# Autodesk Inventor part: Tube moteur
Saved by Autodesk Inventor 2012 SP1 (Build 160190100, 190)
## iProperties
Created: 2014-12
Part Number: Tube moteur
Material: Default
Document SubType Name: Modeling
Designer: Bruno
Density: 1 g/cm^3
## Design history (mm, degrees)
node "Tube moteur1"
node "Tube moteur"
node "Base1"
